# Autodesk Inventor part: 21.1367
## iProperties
Created: 2006-02
Part Number: 21.1367
Material: Steel, Mild
Description: M6X14 SHCS
Document SubType Name: Modeling
Standard: DIN 7984
Designer: Andy Moles
Standards Organization: DIN
Language: en-US
Size Designation: M6 x 12
Categories: <MemberInstance><Categories><Category DisplayName="Fasteners" InternalName="e4da775c-781d-43d5-af7c-5136215cf5a6" Mnemonic="FSTN"><Category DisplayName="Bolts"
Density: 7.86 g/cm^3
Mass: 5.1524 g
Surface Area: 5.76463 cm^2
Volume: 0.655521 cm^3
Author: Andy Moles
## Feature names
1. Body [Revolution]
2. Slot [Extrusion]
3. Fillet1
4. Chamfer1
